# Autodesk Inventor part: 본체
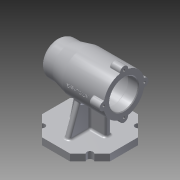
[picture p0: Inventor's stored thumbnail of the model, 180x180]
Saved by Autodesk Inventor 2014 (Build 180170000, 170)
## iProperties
Created: 2021-01
Part Number: 본체
Material: Aluminum 6061
Document SubType Name: Modeling
Designer: kh
Mass: 632.435 g
Surface Area: 613.582 cm^2
Volume: 233.371 cm^3
Density: 2.71 g/cm^3
Appearance: Aluminum - Flat
Author: kh
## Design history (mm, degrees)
sketch "Sketch1" dims "d0" = 100
  geometry: L1 (20.711, 50)-(50, 20.711); L2 (50, 20.711)-(50, -20.711); L3 (50, -20.711)-(20.711, -50); L4 (20.711, -50)-(-20.711, -50); L5 (-20.711, -50)-(-50, -20.711); L6 (-50, -20.711)-(-50, 20.711); L7 (-50, 20.711)-(-20.711, 50); L8 (-20.711, 50)-(20.711, 50); 4 further points
  constraints: 16 end point, 2 coincident, 2 vertical alignment, 1 midpoint, 19 other
extrude "Extrusion1" new body sketch "Sketch1" distance "d1" = 10; taper "d2" = 0 deg
sketch "Sketch2"
  geometry: L1 (50, 20.711)-(20.711, 50) reference; L2 (20.711, 50)-(-20.711, 50) reference; L3 (-20.711, 50)-(-50, 20.711) reference; L4 (-50, 20.711)-(-50, -20.711) reference; L5 (-50, -20.711)-(-20.711, -50) reference; L6 (-20.711, -50)-(20.711, -50) reference; L7 (20.711, -50)-(50, -20.711) reference; L8 (50, -20.711)-(50, 20.711) reference; L9 (-50, 0)-(50, 0); L10 (0, 50)-(0, -50); L11 (0, 0)-(-35.355, 35.355); C1 r 4.5 at (-35.355, 35.355); C2 r 4.5 at (-35.355, -35.355); C3 r 4.5 at (35.355, -35.355); C4 r 4.5 at (35.355, 35.355)
  constraints: 8 midpoint, 6 end point, 4 centre point, 1 coincident
  dimensions: "d3" = 9 diameter of C1; "d6" = 9 diameter of C2; "d7" = 9 diameter of C3; "d8" = 9 diameter of C4
  node "Projected Loop1"
extrude "Extrusion2" cut sketch "Sketch2" distance "d4" = 10; taper "d5" = 0 deg
extrude "Extrusion3" cut sketch "Sketch2" distance "d9" = 10; taper "d10" = 0 deg
sketch "Sketch3"
  geometry: L1 (20.711, 0)-(-20.711, 0) reference; L2 (-50, 0)-(-50, 10) reference; L3 (-50, 75)-(50, 75); L4 (50, 75)-(50, 100); L5 (50, 100)-(30, 100); L6 (30, 100)-(10, 105); L7 (10, 105)-(-50, 105); L8 (-50, 105)-(-50, 75); L9 (-50, 96)-(-35, 96); L10 (-35, 96)-(-35, 96); L11 (-32, 99)-(4, 99); L12 (7, 96)-(7, 96); L13 (7, 96)-(18.7, 96); L14 (19, 95.7)-(19, 92.5); L15 (19, 92.5)-(36.7, 92.5); L16 (37, 92.2)-(37, 91); L17 (37, 91)-(40.7, 91); L18 (41, 90.7)-(41, 85.5); L19 (41, 85.5)-(41, 85.5); L20 (44, 82.5)-(44, 75); A1 r 3 centre (41, 82.5) between (44, 82.5) and (41, 85.5); A2 r 0.3 centre (40.7, 90.7) between (41, 90.7) and (40.7, 91); A3 r 0.3 centre (36.7, 92.2) between (37, 92.2) and (36.7, 92.5); A4 r 0.3 centre (18.7, 95.7) between (19, 95.7) and (18.7, 96); A5 r 3 centre (4, 96) between (7, 96) and (4, 99); A6 r 3 centre (-32, 96) between (-32, 99) and (-35, 96); 3 further points
  constraints: 36 end point, 12 point on circle, 12 tangent, 10 parallel, 6 centre point, 6 perpendicular, 6 point on line, 3 equal radius, 2 collinear, 1 vertical alignment
  dimensions: "d11" = 100 distance of L3.start L3.end; "d12" = 75 distance from line of L2.start L3; "d13" = 60 diameter of L7 L3; "d14" = 50 diameter of L5 L3; "d15" = 20 distance from line of L5.end L4; "d16" = 40 distance from line of L6.end L4; "d17" = 42 diameter of L9 L3; "d18" = 48 diameter of L11 L3; "d19" = 35 diameter of L15 L3; "d20" = 32 diameter of L17 L3; "d21" = 21 diameter of L19 L3; "d22" = 15 distance between parallel lines of L8 L10; "d23" = 42 distance between parallel lines of L12 L10; "d24" = 12 distance between parallel lines of L12 L14; "d25" = 18 distance between parallel lines of L14 L16; "d26" = 4 distance between parallel lines of L16 L18; "d27" = 3 distance between parallel lines of L18 L20; "d28" = 3 radius of A1; "d29" = 0.3 radius of A2; "d31" = 3 radius of A5
revolve "Revolution1" sketch "Sketch3" stored, may be unused: angle "d30" = 90 deg
sketch "Sketch4"
  geometry: C1 r 6 at (-30, 0); 2 further points
  constraints: 2 horizontal alignment, 1 centre point, 1 other
  dimensions: "d32" = 12 diameter of C1
extrude "Extrusion4" join sketch "Sketch4" distance "d33" = 16; taper "d34" = 0 deg
pattern_circular "Circular Pattern1" dims angle "d36" = 360 deg
hole "Hole1" diameter "d40" = 3.242; stored, may be unused: countersink angle "d44" = 90 deg, drill point angle "d46" = 118 deg; dims "d38" = 10, "d39" = 10, "d41" = 8, "d42" = 4, "d43" = 2, "d45" = 10
pattern_circular "Circular Pattern2" dims angle "d48" = 360 deg
sketch "Sketch5"
  geometry: L1 (38.537, 10)-(50, 10) reference; L2 (30.855, 10)-(38.537, 10) reference; L3 (20.711, 10)-(32.173, 10) reference; L4 (-20.711, 10)-(20.711, 10) reference; L5 (-32.173, 10)-(-20.711, 10) reference; L6 (-38.537, 10)-(-30.855, 10) reference; L7 (-50, 10)-(-38.537, 10) reference; L8 (50, 0)-(38.537, 0) reference; L9 (38.537, 0)-(30.855, 0) reference; L10 (32.173, 0)-(20.711, 0) reference; L11 (20.711, 0)-(-20.711, 0) reference; L12 (-20.711, 0)-(-32.173, 0) reference; L13 (-30.855, 0)-(-38.537, 0) reference; L14 (-38.537, 0)-(-50, 0) reference; L15 (-34, 45)-(10, 45) reference; L16 (10, 45)-(30, 50) reference; L17 (27, 10)-(22.139, 35.006); L18 (-27, 10)-(-27, 35.006); L19 (27, 10)-(-27, 10); 1 further point
  constraints: 6 end point, 2 point on line, 1 collinear, 1 perpendicular
  dimensions: "d50" = 101 deg angle of L17 L3; "d51" = 23 distance of L1.end L17.start; "d52" = 23 distance from line of L7.start L18
feature "Rib1" sketch "Sketch5" dims "d53" = 1, "d54" = 8, "d55" = 0, "d56" = 0, "d57" = 1, "d58" = 1
sketch "Sketch6"
  geometry: L1 (20.711, 10)-(-20.711, 10) reference; L2 (-20.711, 10)-(-32.173, 10) reference; L3 (-38.537, 10)-(-30.855, 10) reference; L4 (-38.537, 10)-(-50, 10) reference; L5 (32.173, 10)-(20.711, 10) reference; L6 (30.855, 10)-(38.537, 10) reference; L7 (50, 10)-(38.537, 10) reference; L8 (-35, 10)-(-19.606, 52.293); L9 (35, 10)-(19.606, 52.293); L10 (-35, 10)-(35, 10); C1 r 1.621 at (-30, 75) reference; C2 r 1.621 at (0, 45) reference; C3 r 1.621 at (30, 75) reference; C4 r 1.621 at (0, 105) reference; C5 r 21 at (0, 75) reference; A1 r 30 centre (0, 75) between (-29.4, 69.03) and (-5.97, 45.6) reference; A2 r 6 centre (0, 45) between (-5.97, 45.6) and (5.97, 45.6) reference; A3 r 30 centre (0, 75) between (5.97, 45.6) and (29.4, 69.03) reference; A4 r 6 centre (30, 75) between (29.4, 69.03) and (29.4, 80.97) reference; A5 r 30 centre (0, 75) between (29.4, 80.97) and (5.97, 104.4) reference; A6 r 6 centre (0, 105) between (5.97, 104.4) and (-5.97, 104.4) reference; A7 r 30 centre (0, 75) between (-5.97, 104.4) and (-29.4, 80.97) reference; A8 r 6 centre (-30, 75) between (-29.4, 80.97) and (-29.4, 69.03) reference; A9 r 30 centre (0, 75) between (-19.606, 52.293) and (19.606, 52.293); 1 further point
  constraints: 6 end point, 5 point on circle, 2 point on line, 1 centre point, 1 collinear
  dimensions: "d59" = 15 distance of L8.start L4.end; "d60" = 15 distance of L7.start L9.start; "d61" = 110 deg angle of L7 L9; "d62" = 110 deg angle of L4 L8
extrude "Extrusion5" join sketch "Sketch6" stored distance "d63" = 8; taper "d64" = 0 deg
fillet "Fillet1" dims "d65" = 10
fillet "Fillet2" dims "d66" = 3
fillet "Fillet3" dims "d67" = 1
fillet "Fillet6" dims "d70" = 3
fillet "Fillet8" dims "d72" = 3
fillet "Fillet9" dims "d73" = 3
chamfer "Chamfer1" distance "d74" = 1; stored, may be unused: second distance "d75" = 2, angle "d76" = 45 deg
workplane "Work Plane2"
sketch "Sketch7"
  geometry: L1 (-17.033, 77.402)-(41.033, 77.402); L2 (41.033, 77.402)-(41.033, 72.598); L3 (41.033, 72.598)-(-17.033, 72.598); L4 (-17.033, 72.598)-(-17.033, 77.402); L5 (-17.033, 75)-(41.033, 75); L6 (12, 77.402)-(12, 72.598); L7 (-7, 96)-(-7, 54) reference; L8 (50, 104.226)-(50, 81.771) reference; L9 (-50, 60)-(-50, 90) reference; 3 further points
  constraints: 6 midpoint, 4 end point, 1 horizontal alignment, 2 other
  dimensions: "d78" = 38 distance between parallel lines of L8 L6
emboss "Emboss1" sketch "Sketch7" dims "d79" = 0.5, "d80" = 0
fillet "Fillet10" dims "d81" = 3
body "Solid1"
node "Projected Loop2"
other parameters: "d77" = -51
